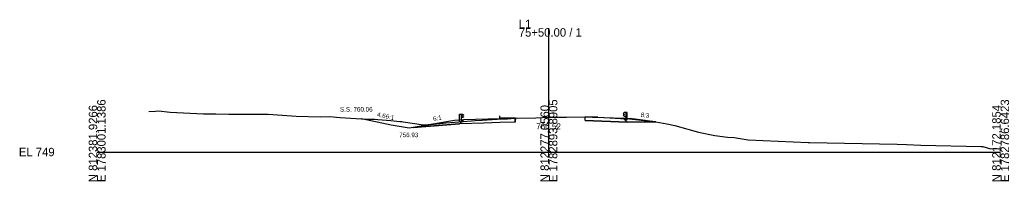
# Model space of a CAD drawing. Extents: x 5574 to 10203, y -10 to 9546.
# Drawn here: x 8574.3 to 8902.8, y 3490.3 to 3543.9 of the extents above; entities that cross this region are included whole.
import ezdxf

# ---------------------------------------------------------------- set-up
doc = ezdxf.new("R2010")
doc.units = 0
for name, color, linetype in [('Exist Cross Section Cell', 7, 'Continuous'), ('Exist XS Center Line Elevation Label', 7, 'Continuous'), ('Exist XS Ground Line', 7, 'Continuous'), ('Prop XS Ditch Slope Text', 7, 'Continuous'), ('Prop XS Ditch Standard Text', 7, 'Continuous'), ('Prop XS Dump Level', 7, 'Continuous'), ('Prop XS Earthwork Shape', 7, 'Continuous'), ('Prop XS EOT Tick Mark', 7, 'Continuous'), ('Prop XS Finish Grade', 7, 'Continuous'), ('Prop XS Finish Grade Earthwork', 7, 'Continuous'), ('Prop XS Finish Grade Paved Shoulder', 7, 'Continuous'), ('Prop XS Finish Grade Pavement', 7, 'Continuous'), ('Prop XS Guardrail', 7, 'Continuous'), ('Prop XS Hydro Typical Ditch Data', 7, 'Continuous'), ('Prop XS Pvmt Edge Slope', 7, 'Continuous'), ('Prop XS Side Slope Text', 7, 'Continuous'), ('Prop XS SS Elevation Text', 7, 'Continuous'), ('Prop XS Subgrade Earthwork', 7, 'Continuous'), ('Scratch_Level_3', 7, 'Continuous'), ('Scratch_Level_6', 7, 'Continuous')]:
    doc.layers.add(name, color=color, linetype=linetype)

msp = doc.modelspace()

# ---------------------------------------------------------------- linework, layer by layer
at = {"layer": 'Exist Cross Section Cell'}
for p, q in [((8750, 3500), (8750, 3541.11)), ((8600, 3500), (8750, 3500)), ((8750, 3500), (8900, 3500))]:
    msp.add_line(p, q, dxfattribs=at)
at = {"layer": 'Exist XS Ground Line'}
for p, q in [((8617.21, 3513.49), (8619.34, 3513.57)), ((8619.34, 3513.57), (8620.4, 3513.7)), ((8620.4, 3513.7), (8624.19, 3513.23)), ((8624.19, 3513.23), (8635.32, 3512.69)), ((8635.32, 3512.69), (8639.43, 3512.69)), ((8639.43, 3512.69), (8643.68, 3512.54)), ((8643.68, 3512.54), (8652.29, 3512.52)), ((8652.29, 3512.52), (8656.79, 3512.61)), ((8656.79, 3512.61), (8666.04, 3511.96)), ((8666.04, 3511.96), (8674.16, 3511.72)), ((8674.16, 3511.72), (8677.09, 3511.77)), ((8677.09, 3511.77), (8680.72, 3511.44)), ((8680.72, 3511.44), (8689.52, 3510.96)), ((8689.52, 3510.96), (8692.18, 3510.87)), ((8692.18, 3510.87), (8693.15, 3510.78)), ((8693.15, 3510.78), (8697.5, 3510.44)), ((8697.5, 3510.44), (8700.5, 3510.14)), ((8700.5, 3510.14), (8701.12, 3510.13)), ((8701.12, 3510.13), (8701.6, 3510.07)), ((8701.6, 3510.07), (8708.4, 3509.06)), ((8708.4, 3509.06), (8711.31, 3509.22)), ((8711.31, 3509.22), (8711.78, 3509.25)), ((8711.78, 3509.25), (8715.75, 3509.66)), ((8715.75, 3509.66), (8718.8, 3509.88)), ((8718.8, 3509.88), (8721.49, 3510.18)), ((8721.49, 3510.18), (8724.25, 3510.38)), ((8724.25, 3510.38), (8725.53, 3510.43)), ((8725.53, 3510.43), (8727.87, 3510.6)), ((8727.87, 3510.6), (8734.49, 3510.97)), ((8734.49, 3510.97), (8736.29, 3511.07)), ((8736.29, 3511.07), (8738.73, 3511.19)), ((8738.73, 3511.19), (8745.61, 3511.4)), ((8745.61, 3511.4), (8750, 3511.52)), ((8750, 3511.52), (8750.83, 3511.55)), ((8750.83, 3511.55), (8755.85, 3511.61)), ((8755.85, 3511.61), (8762.21, 3511.71)), ((8762.21, 3511.71), (8764.46, 3511.62)), ((8764.46, 3511.62), (8766.09, 3511.55)), ((8766.09, 3511.55), (8770.21, 3511.3)), ((8770.21, 3511.3), (8773.74, 3511.12)), ((8773.74, 3511.12), (8777.78, 3511.12)), ((8777.78, 3511.12), (8781.98, 3510.59)), ((8781.98, 3510.59), (8785.53, 3510.02)), ((8785.53, 3510.02), (8789.16, 3509.33)), ((8789.16, 3509.33), (8791.83, 3508.77)), ((8791.83, 3508.77), (8799.66, 3506.64)), ((8799.66, 3506.64), (8805.06, 3505.5)), ((8805.06, 3505.5), (8809.34, 3504.98)), ((8809.34, 3504.98), (8811.55, 3504.78)), ((8811.55, 3504.78), (8816.18, 3504.1)), ((8816.18, 3504.1), (8836.05, 3503.21)), ((8836.05, 3503.21), (8836.48, 3503.2)), ((8836.48, 3503.2), (8865.61, 3502.59)), ((8865.61, 3502.59), (8868.69, 3502.49)), ((8868.69, 3502.49), (8873.44, 3502.32)), ((8873.44, 3502.32), (8893.56, 3501.87)), ((8893.56, 3501.87), (8894.06, 3501.86)), ((8894.06, 3501.86), (8896.6, 3501.1)), ((8896.6, 3501.1), (8897.5, 3501.2)), ((8897.5, 3501.2), (8898.14, 3501.24)), ((8898.14, 3501.24), (8899.29, 3501.03)), ((8899.29, 3501.03), (8900, 3501.22))]:
    msp.add_line(p, q, dxfattribs=at)
at = {"layer": 'Prop XS Dump Level'}
msp.add_line((8738.74, 3511.3), (8733.65, 3511.2), dxfattribs=at)
at = {"layer": 'Prop XS Earthwork Shape'}
for points in [[(8687.77, 3511.06), (8689.52, 3510.96), (8692.18, 3510.87), (8693.15, 3510.78), (8697.5, 3510.44), (8700.5, 3510.14), (8701.12, 3510.13), (8701.6, 3510.07), (8708.4, 3509.06), (8711.31, 3509.22), (8711.78, 3509.25), (8715.75, 3509.66), (8718.8, 3509.88), (8721.49, 3510.18), (8724.25, 3510.38), (8725.53, 3510.43), (8727.87, 3510.6), (8734.49, 3510.97), (8736.29, 3511.07), (8738.73, 3511.19), (8738.75, 3511.19), (8738.75, 3509.94), (8733.69, 3509.79), (8728.36, 3509.63), (8720.36, 3509.38), (8704.96, 3508.15), (8703.65, 3507.93), (8697.65, 3508.93)], [(8781.98, 3510.59), (8785.53, 3510.02), (8776, 3509.9), (8762, 3510.46), (8762, 3511.71), (8762.21, 3511.71), (8764.46, 3511.62), (8766.09, 3511.55), (8770.21, 3511.3), (8773.74, 3511.12), (8777.78, 3511.12)]]:
    msp.add_lwpolyline(points, close=True, dxfattribs=at)
at = {"layer": 'Prop XS EOT Tick Mark'}
msp.add_line((8733.65, 3511.04), (8733.65, 3512.04), dxfattribs=at)
at = {"layer": 'Prop XS Finish Grade'}
for p, q in [((8718.65, 3510.43), (8704.96, 3508.15)), ((8721.65, 3510.67), (8718.65, 3510.43)), ((8774.7, 3511.2), (8777.7, 3510.96)), ((8777.7, 3510.96), (8785.53, 3510.02))]:
    msp.add_line(p, q, dxfattribs=at)
at = {"layer": 'Prop XS Finish Grade Earthwork'}
for p, q in [((8697.65, 3508.93), (8687.77, 3511.06)), ((8703.65, 3507.93), (8697.65, 3508.93)), ((8704.96, 3508.15), (8703.65, 3507.93))]:
    msp.add_line(p, q, dxfattribs=at)
at = {"layer": 'Prop XS Finish Grade Paved Shoulder'}
msp.add_line((8733.65, 3511.04), (8721.65, 3510.67), dxfattribs=at)
at = {"layer": 'Prop XS Finish Grade Pavement'}
for p, q in [((8738.75, 3511.19), (8733.65, 3511.04)), ((8762, 3511.71), (8774.7, 3511.2))]:
    msp.add_line(p, q, dxfattribs=at)
at = {"layer": 'Prop XS Guardrail'}
for p, q in [((8720.33, 3512.55), (8720.83, 3512.55)), ((8720.33, 3510.05), (8720.33, 3512.55)), ((8720.83, 3512.55), (8721.33, 3512.55)), ((8720.83, 3512.55), (8720.83, 3510.05)), ((8721.33, 3512.55), (8721.62, 3512.35)), ((8721.62, 3512.23), (8721.33, 3512.03)), ((8721.33, 3512.03), (8721.33, 3511.93)), ((8721.62, 3512.35), (8721.65, 3512.29)), ((8721.65, 3512.29), (8721.62, 3512.23)), ((8774.73, 3512.87), (8774.7, 3512.81)), ((8774.7, 3512.81), (8774.73, 3512.75)), ((8774.73, 3512.26), (8774.7, 3512.2)), ((8774.7, 3512.2), (8774.73, 3512.14)), ((8775.02, 3513.07), (8774.73, 3512.87)), ((8774.73, 3512.75), (8775.02, 3512.55)), ((8775.02, 3512.46), (8774.73, 3512.26)), ((8774.73, 3512.14), (8775.02, 3511.94)), ((8775.52, 3513.07), (8775.02, 3513.07)), ((8775.02, 3512.55), (8775.02, 3512.46)), ((8776.02, 3513.07), (8775.52, 3513.07)), ((8775.52, 3513.07), (8775.52, 3510.57)), ((8776.02, 3510.57), (8776.02, 3513.07)), ((8721.33, 3511.41), (8720.83, 3511.41)), ((8721.33, 3511.93), (8721.62, 3511.73)), ((8721.62, 3511.61), (8721.33, 3511.41)), ((8721.62, 3511.73), (8721.65, 3511.67)), ((8721.65, 3511.67), (8721.62, 3511.61)), ((8775.02, 3511.94), (8775.52, 3511.94))]:
    msp.add_line(p, q, dxfattribs=at)
at = {"layer": 'Prop XS Hydro Typical Ditch Data'}
for p, q in [((8697.65, 3508.93), (8687.77, 3511.06)), ((8703.65, 3507.93), (8697.65, 3508.93))]:
    msp.add_line(p, q, dxfattribs=at)
at = {"layer": 'Prop XS Pvmt Edge Slope'}
for p, q in [((8721.65, 3510.67), (8720.36, 3509.38)), ((8774.7, 3511.2), (8776, 3509.9))]:
    msp.add_line(p, q, dxfattribs=at)
at = {"layer": 'Prop XS Subgrade Earthwork'}
for p, q in [((8720.36, 3509.38), (8704.96, 3508.15)), ((8728.36, 3509.63), (8720.36, 3509.38)), ((8733.69, 3509.79), (8728.36, 3509.63)), ((8738.75, 3509.94), (8733.69, 3509.79)), ((8738.75, 3509.94), (8738.75, 3511.19)), ((8762, 3510.46), (8762, 3511.71)), ((8762, 3510.46), (8776, 3509.9)), ((8776, 3509.9), (8785.53, 3510.02))]:
    msp.add_line(p, q, dxfattribs=at)
at = {"layer": 'Scratch_Level_3'}
for p, q in [((8718.65, 3510.43), (8704.96, 3508.15)), ((8704.96, 3508.15), (8720.36, 3509.38)), ((8721.65, 3510.67), (8718.65, 3510.43)), ((8720.36, 3509.38), (8721.65, 3510.67)), ((8777.7, 3510.96), (8774.7, 3511.2)), ((8774.7, 3511.2), (8776, 3509.9)), ((8776, 3509.9), (8785.53, 3510.02)), ((8785.53, 3510.02), (8777.7, 3510.96))]:
    msp.add_line(p, q, dxfattribs=at)
at = {"layer": 'Scratch_Level_6'}
for points in [[(8738.75, 3509.94), (8733.69, 3509.79), (8728.36, 3509.63), (8720.36, 3509.38), (8704.96, 3508.15), (8711.38, 3509.22), (8711.78, 3509.25), (8715.75, 3509.66), (8718.8, 3509.88), (8721.49, 3510.18), (8724.25, 3510.38), (8725.53, 3510.43), (8727.87, 3510.6), (8734.49, 3510.97), (8736.29, 3511.07), (8738.73, 3511.19), (8738.75, 3511.19)], [(8777.7, 3510.96), (8785.53, 3510.02), (8776, 3509.9), (8762, 3510.46), (8762, 3511.71), (8766.25, 3511.54), (8770.21, 3511.3), (8773.74, 3511.12), (8775.72, 3511.12)], [(8764.46, 3511.62), (8766.09, 3511.55), (8766.25, 3511.54), (8762, 3511.71), (8762.21, 3511.71)]]:
    msp.add_lwpolyline(points, close=True, dxfattribs=at)

# ---------------------------------------------------------------- texts
at = {"layer": 'Exist Cross Section Cell'}
for s, p in [('L1', (8740, 3541.11)), ('75+50.00 / 1', (8740, 3538.31)), ('EL 749', (8574, 3498.6))]:
    msp.add_text(s, height=2.8, dxfattribs=at).set_placement(p)
for s, p in [('N 812381.9266', (8600, 3490)), ('E 1783001.1386', (8602.8, 3490)), ('N 812277.0560', (8750, 3490)), ('E 1782893.8905', (8752.8, 3490)), ('N 812172.1854', (8900, 3490)), ('E 1782786.6423', (8902.8, 3490))]:
    msp.add_text(s, height=2.8, rotation=90, dxfattribs=at).set_placement(p)
at = {"layer": 'Exist XS Center Line Elevation Label'}
msp.add_text('760.52', height=2, dxfattribs=at).set_placement((8745.79, 3507.52))
at = {"layer": 'Prop XS Ditch Slope Text'}
for s, rotation, p in [('6:1', 9.4623, (8711.65, 3510.28)), ('8:3', 353.1637, (8780.4, 3511.68))]:
    msp.add_text(s, height=1.5, rotation=rotation, dxfattribs=at).set_placement(p)
at = {"layer": 'Prop XS Ditch Standard Text'}
msp.add_text('756.93', height=1.5, dxfattribs=at).set_placement((8700.3, 3504.93))
at = {"layer": 'Prop XS Dump Level'}
for s, height, p in [('Case4', 0.04, (8721.65, 3510.24)), ('Eop', 0.3, (8738.75, 3510.89))]:
    msp.add_text(s, height=height, dxfattribs=at).set_placement(p)
at = {"layer": 'Prop XS Side Slope Text'}
msp.add_text('4.66:1', height=1.5, rotation=347.8771, dxfattribs=at).set_placement((8692.83, 3511.78))
at = {"layer": 'Prop XS SS Elevation Text'}
msp.add_text('S.S. 760.06', height=1.5, dxfattribs=at).set_placement((8680.63, 3513.43))

doc.saveas('drawing.dxf')
